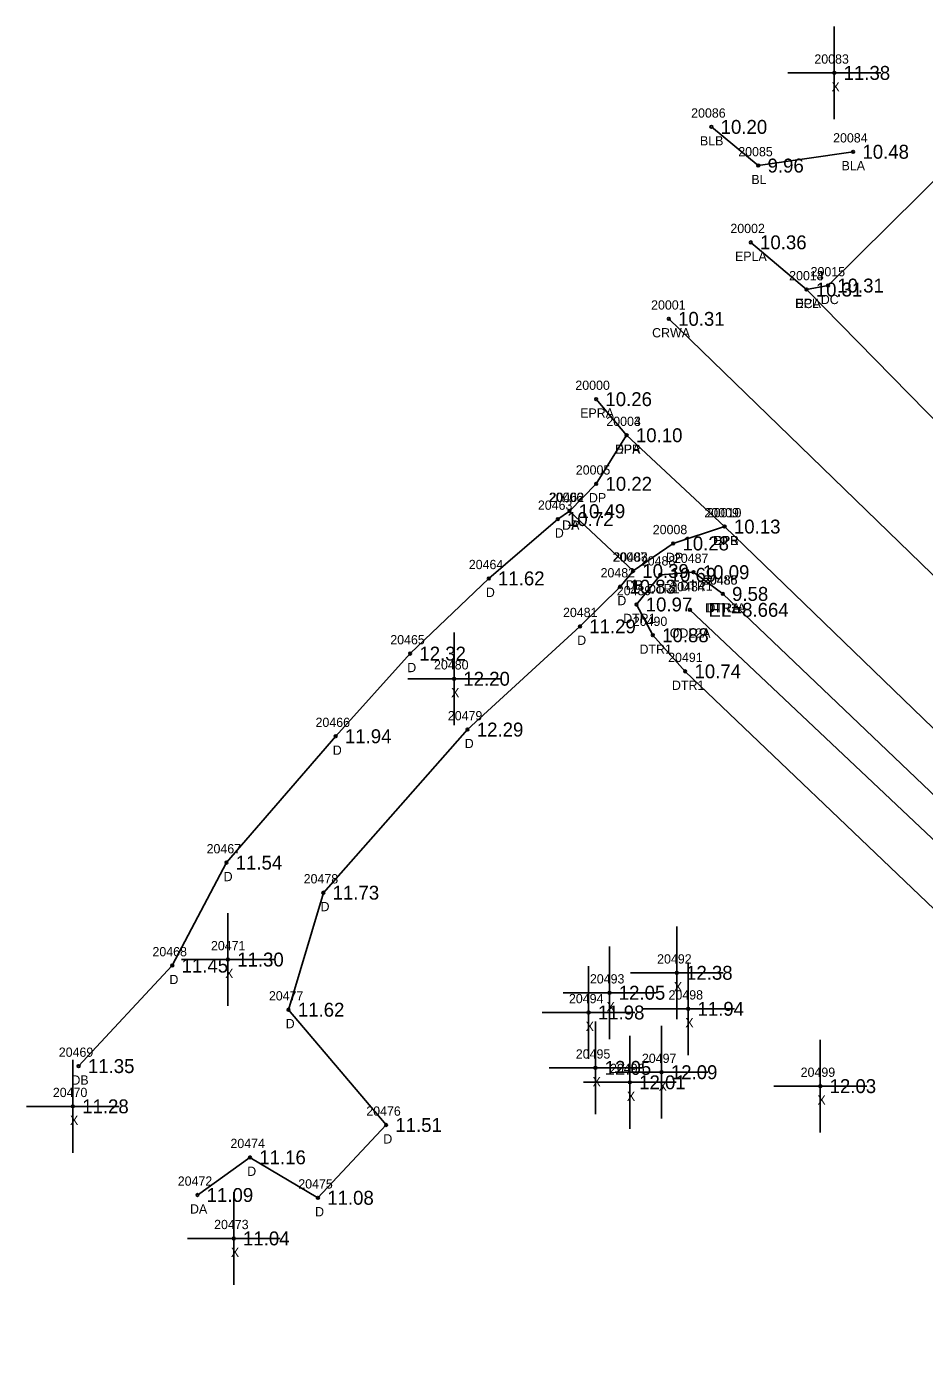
# Model space of a CAD drawing. Extents: x 2608745 to 2610333, y 641917 to 643463.
# Drawn here: x 2608745.5 to 2608842.3, y 643262.1 to 643405.2 of the extents above; entities that cross this region are included whole.
import ezdxf

# ---------------------------------------------------------------- set-up
doc = ezdxf.new("R2010")
doc.units = 0
for name, color, linetype in [('RD_DTM_BkLn1', 7, 'Continuous'), ('RD_DTM_BkLn_txCode', 7, 'Continuous'), ('RD_EX_Conc', 7, 'Continuous'), ('RD_EX_Conc_txCode', 7, 'Continuous'), ('RD_EX_Driveway', 7, 'Continuous'), ('RD_EX_Driveway_txCode', 7, 'Continuous'), ('RD_EX_H2O', 7, 'Continuous'), ('RD_EX_H2O_txCode', 7, 'Continuous'), ('RD_EX_Misc', 7, 'Continuous'), ('RD_EX_Misc_txCode', 7, 'Continuous'), ('RD_EX_Road', 7, 'Continuous'), ('RD_EX_Road_txCode', 7, 'Continuous'), ('RD_EX_TX_Conc_ELEV', 7, 'Continuous'), ('RD_EX_TX_Driveway_ELEV', 7, 'Continuous'), ('RD_EX_TX_H2O_ELEV', 7, 'Continuous'), ('RD_EX_TX_Misc_ELEV', 7, 'Continuous'), ('RD_EX_TX_Road_ELEV', 7, 'Continuous'), ('RD_HC_Survey_ELEV', 7, 'Continuous'), ('RD_HC_Survey_txCode', 7, 'Continuous'), ('RD_SMD_Locator', 7, 'Continuous')]:
    doc.layers.add(name, color=color, linetype=linetype)

msp = doc.modelspace()

# ---------------------------------------------------------------- linework, layer by layer
at = {"layer": 'RD_DTM_BkLn1'}
for points in [[(2608834.61, 643391.67), (2608824.38, 643390.18), (2608819.32, 643394.35)], [(2608814.73, 643373.65), (2608890.45, 643300.26), (2608962.19, 643231.31), (2609034.91, 643161.19), (2609108.48, 643089.9), (2609179.19, 643022.29), (2609255.71, 642948.78), (2609335.19, 642871.73), (2609410.7, 642798.48), (2609491.67, 642719.95), (2609518.07, 642695.15)]]:
    msp.add_lwpolyline(points, dxfattribs=at)
at = {"layer": 'RD_EX_Conc'}
msp.add_lwpolyline([(2608829.58, 643376.81), (2608831.9, 643377.24), (2608848.38, 643393.52)], dxfattribs=at)
at = {"layer": 'RD_EX_Driveway'}
for points in [[(2608810.18, 643361.1), (2608806.9, 643355.86), (2608804.01, 643352.91), (2608810.87, 643346.46), (2608815.2, 643349.43), (2608820.75, 643351.25)], [(2608804.01, 643352.91), (2608802.75, 643352.06), (2608795.31, 643345.66), (2608786.83, 643337.55), (2608778.8, 643328.64), (2608767.02, 643315.01), (2608761.18, 643303.91), (2608751.08, 643293.07)], [(2608763.89, 643279.17), (2608769.56, 643283.23), (2608776.89, 643278.87), (2608784.24, 643286.72), (2608773.72, 643299.15), (2608777.47, 643311.77), (2608793.02, 643329.36), (2608805.15, 643340.49), (2608809.48, 643344.77), (2608810.87, 643346.46)]]:
    msp.add_lwpolyline(points, dxfattribs=at)
at = {"layer": 'RD_EX_H2O'}
for points in [[(2608820.55, 643343.99), (2608817.4, 643346.33), (2608813.82, 643346.05), (2608811.24, 643342.85), (2608813.01, 643339.53), (2608816.5, 643335.64), (2608871.77, 643282.86), (2608887.42, 643272.57)], [(2608820.55, 643343.99), (2608878.38, 643288.9), (2608899.7, 643269.64), (2608901.3, 643266.14), (2608896.99, 643263), (2608887.42, 643272.57)], [(2608817.01, 643342.27), (2608875.55, 643287.01), (2608897.37, 643266.54)]]:
    msp.add_lwpolyline(points, dxfattribs=at)
at = {"layer": 'RD_EX_Misc'}
for p, q in [((2608832.58, 643395.17), (2608832.58, 643405.17)), ((2608827.58, 643400.17), (2608837.58, 643400.17)), ((2608791.57, 643329.84), (2608791.57, 643339.84)), ((2608786.57, 643334.84), (2608796.57, 643334.84)), ((2608767.18, 643299.56), (2608767.18, 643309.56)), ((2608815.59, 643298.13), (2608815.59, 643308.13)), ((2608808.33, 643295.98), (2608808.33, 643305.98)), ((2608762.18, 643304.56), (2608772.18, 643304.56)), ((2608816.82, 643294.25), (2608816.82, 643304.25)), ((2608806.08, 643293.85), (2608806.08, 643303.85)), ((2608810.59, 643303.13), (2608820.59, 643303.13)), ((2608803.33, 643300.98), (2608813.33, 643300.98)), ((2608801.08, 643298.85), (2608811.08, 643298.85)), ((2608811.82, 643299.25), (2608821.82, 643299.25)), ((2608806.81, 643287.88), (2608806.81, 643297.88)), ((2608813.95, 643287.41), (2608813.95, 643297.41)), ((2608810.53, 643286.32), (2608810.53, 643296.32)), ((2608831.07, 643285.91), (2608831.07, 643295.91)), ((2608750.46, 643283.73), (2608750.46, 643293.73)), ((2608801.81, 643292.88), (2608811.81, 643292.88)), ((2608808.95, 643292.41), (2608818.95, 643292.41)), ((2608805.53, 643291.32), (2608815.53, 643291.32)), ((2608826.07, 643290.91), (2608836.07, 643290.91)), ((2608745.46, 643288.73), (2608755.46, 643288.73)), ((2608767.81, 643269.49), (2608767.81, 643279.49)), ((2608762.81, 643274.49), (2608772.81, 643274.49))]:
    msp.add_line(p, q, dxfattribs=at)
at = {"layer": 'RD_EX_Road'}
for points in [[(2608823.57, 643381.9), (2608829.58, 643376.81), (2608846.19, 643359.9), (2608852.07, 643354.1), (2608873.12, 643334.61), (2608877.91, 643330.13), (2608897.26, 643311.51), (2608898.77, 643309.3), (2608970.3, 643240.18), (2609042.49, 643170.94), (2609058.51, 643155.46), (2609096.06, 643119.37)], [(2608806.89, 643364.99), (2608810.18, 643361.1), (2608820.75, 643351.25), (2608881.81, 643292.24), (2608917.83, 643257.49), (2608933.21, 643242.71), (2608954.07, 643222.83), (2609026.06, 643154.19), (2609039.6, 643139.96), (2609073.88, 643106.95), (2609100.48, 643081.89), (2609124.19, 643058.87), (2609171.61, 643013.71), (2609183.19, 643002.28), (2609197.91, 642988.37), (2609247.59, 642940.95), (2609328.02, 642863.6), (2609402.61, 642790.3), (2609474.23, 642720.69), (2609483.84, 642711.58), (2609495.78, 642699.92), (2609509.81, 642686.45)]]:
    msp.add_lwpolyline(points, dxfattribs=at)
at = {"layer": 'RD_SMD_Locator'}
for centre in [(2608832.58, 643400.17), (2608819.32, 643394.35), (2608834.61, 643391.67), (2608824.38, 643390.18), (2608823.57, 643381.9), (2608831.9, 643377.24), (2608829.58, 643376.81), (2608829.58, 643376.81), (2608814.73, 643373.65), (2608806.89, 643364.99), (2608810.18, 643361.1), (2608810.18, 643361.1), (2608806.9, 643355.86), (2608804.01, 643352.91), (2608804.01, 643352.91), (2608802.75, 643352.06), (2608820.75, 643351.25), (2608820.75, 643351.25), (2608815.2, 643349.43), (2608795.31, 643345.66), (2608810.87, 643346.46), (2608810.87, 643346.46), (2608813.82, 643346.05), (2608817.4, 643346.33), (2608809.48, 643344.77), (2608811.24, 643342.85), (2608820.55, 643343.99), (2608820.55, 643343.99), (2608817.01, 643342.27), (2608805.15, 643340.49), (2608813.01, 643339.53), (2608786.83, 643337.55), (2608816.5, 643335.64), (2608791.57, 643334.84), (2608778.8, 643328.64), (2608793.02, 643329.36), (2608767.02, 643315.01), (2608777.47, 643311.77), (2608767.18, 643304.56), (2608761.18, 643303.91), (2608815.59, 643303.13), (2608808.33, 643300.98), (2608773.72, 643299.15), (2608806.08, 643298.85), (2608816.82, 643299.25), (2608751.08, 643293.07), (2608806.81, 643292.88), (2608810.53, 643291.32), (2608813.95, 643292.41), (2608831.07, 643290.91), (2608750.46, 643288.73), (2608784.24, 643286.72), (2608769.56, 643283.23), (2608763.89, 643279.17), (2608776.89, 643278.87), (2608767.81, 643274.49)]:
    msp.add_circle(centre, 0.15, dxfattribs=at)

# ---------------------------------------------------------------- texts
at = {"layer": 'RD_DTM_BkLn_txCode'}
for s, p in [('20086', (2608817.14, 643395.35)), ('BLB', (2608818.09, 643392.35)), ('20084', (2608832.45, 643392.67)), ('20085', (2608822.22, 643391.18)), ('BLA', (2608833.36, 643389.67)), ('BL', (2608823.63, 643388.18))]:
    msp.add_text(s, height=1, dxfattribs=at).set_placement(p)
at = {"layer": 'RD_EX_Conc_txCode'}
for s, p in [('20014', (2608827.71, 643377.81)), ('20015', (2608830.02, 643378.24)), ('DCA', (2608828.32, 643374.81)), ('DC', (2608831.12, 643375.24))]:
    msp.add_text(s, height=1, dxfattribs=at).set_placement(p)
at = {"layer": 'RD_EX_Driveway_txCode'}
for s, p in [('20004', (2608807.99, 643362.1)), ('DPA', (2608808.92, 643359.1)), ('20005', (2608804.7, 643356.86)), ('20006', (2608801.79, 643353.91)), ('20462', (2608801.87, 643353.91)), ('DP', (2608806.12, 643353.86)), ('20463', (2608800.61, 643353.06)), ('20009', (2608818.56, 643352.25)), ('DA', (2608803.22, 643350.91)), ('DP', (2608803.24, 643350.91)), ('D', (2608802.44, 643350.06)), ('20008', (2608813, 643350.43)), ('DPB', (2608819.5, 643349.25)), ('20464', (2608793.16, 643346.66)), ('20007', (2608808.67, 643347.46)), ('20483', (2608808.75, 643347.46)), ('DP', (2608814.42, 643347.43)), ('20482', (2608807.37, 643345.77)), ('D', (2608795, 643343.66)), ('DP', (2608810.09, 643344.46)), ('DB', (2608810.09, 643344.46)), ('D', (2608809.18, 643342.77)), ('20481', (2608803.32, 643341.49)), ('20465', (2608784.69, 643338.55)), ('D', (2608804.85, 643338.49)), ('D', (2608786.52, 643335.55)), ('20466', (2608776.63, 643329.64)), ('20479', (2608790.9, 643330.36)), ('D', (2608778.49, 643326.64)), ('D', (2608792.72, 643327.36)), ('20467', (2608764.88, 643316.01)), ('D', (2608766.72, 643313.01)), ('20478', (2608775.35, 643312.77)), ('D', (2608777.17, 643309.77)), ('20468', (2608759.04, 643304.91)), ('D', (2608760.87, 643301.91)), ('20477', (2608771.6, 643300.15)), ('D', (2608773.41, 643297.15)), ('20469', (2608748.94, 643294.07)), ('DB', (2608750.3, 643291.07)), ('20476', (2608782.1, 643287.72)), ('D', (2608783.94, 643284.72)), ('20474', (2608767.45, 643284.23)), ('D', (2608769.26, 643281.23)), ('20472', (2608761.77, 643280.17)), ('20475', (2608774.77, 643279.87)), ('DA', (2608763.09, 643277.17)), ('D', (2608776.58, 643276.87))]:
    msp.add_text(s, height=1, dxfattribs=at).set_placement(p)
at = {"layer": 'RD_EX_H2O_txCode'}
for s, p in [('20488', (2608811.71, 643347.05)), ('20487', (2608815.28, 643347.33)), ('20486', (2608818.4, 643344.99)), ('20485', (2608818.43, 643344.99)), ('20489', (2608809.12, 643343.85)), ('DTR1', (2608812.39, 643344.05)), ('20484', (2608814.89, 643344.27)), ('DTR1', (2608815.97, 643344.33)), ('DTR1A', (2608818.63, 643341.99)), ('DTRA', (2608818.79, 643341.99)), ('DTR1', (2608809.81, 643340.85)), ('20490', (2608810.85, 643340.53)), ('ODL2A', (2608814.83, 643339.27)), ('DTR1', (2608811.57, 643337.53)), ('20491', (2608814.66, 643336.64)), ('DTR1', (2608815.07, 643333.64))]:
    msp.add_text(s, height=1, dxfattribs=at).set_placement(p)
at = {"layer": 'RD_EX_Misc_txCode'}
for s, p in [('20083', (2608830.43, 643401.17)), ('X', (2608832.27, 643398.17)), ('20480', (2608789.41, 643335.84)), ('X', (2608791.25, 643332.84)), ('20471', (2608765.35, 643305.56)), ('20492', (2608813.47, 643304.13)), ('X', (2608766.87, 643302.56)), ('20493', (2608806.22, 643301.98)), ('X', (2608815.27, 643301.13)), ('20494', (2608803.96, 643299.85)), ('X', (2608808.02, 643298.98)), ('20498', (2608814.7, 643300.25)), ('X', (2608805.76, 643296.85)), ('X', (2608816.51, 643297.25)), ('20495', (2608804.7, 643293.88)), ('20497', (2608811.83, 643293.41)), ('20496', (2608808.39, 643292.32)), ('20499', (2608828.95, 643291.91)), ('X', (2608806.5, 643290.88)), ('X', (2608813.63, 643290.41)), ('20470', (2608748.3, 643289.73)), ('X', (2608810.21, 643289.32)), ('X', (2608830.76, 643288.91)), ('X', (2608750.15, 643286.73)), ('20473', (2608765.69, 643275.49)), ('X', (2608767.5, 643272.49))]:
    msp.add_text(s, height=1, dxfattribs=at).set_placement(p)
at = {"layer": 'RD_EX_Road_txCode'}
for s, p in [('20002', (2608821.37, 643382.9)), ('EPLA', (2608821.87, 643379.9)), ('20013', (2608827.71, 643377.81)), ('EPL', (2608828.38, 643374.81)), ('20000', (2608804.65, 643365.99)), ('EPRA', (2608805.17, 643362.99)), ('20003', (2608807.99, 643362.1)), ('EPR', (2608808.96, 643359.1)), ('20010', (2608818.84, 643352.25)), ('EPR', (2608819.53, 643349.25))]:
    msp.add_text(s, height=1, dxfattribs=at).set_placement(p)
at = {"layer": 'RD_EX_TX_Conc_ELEV'}
for p in [(2608830.58, 643376.06), (2608832.9, 643376.49)]:
    msp.add_text('10.31', height=1.5, dxfattribs=at).set_placement(p)
at = {"layer": 'RD_EX_TX_Driveway_ELEV'}
for s, p in [('10.10', (2608811.18, 643360.35)), ('10.22', (2608807.9, 643355.11)), ('10.49', (2608805.01, 643352.16)), ('10.49', (2608805.01, 643352.16)), ('10.72', (2608803.75, 643351.31)), ('10.13', (2608821.75, 643350.5)), ('10.28', (2608816.2, 643348.68)), ('10.39', (2608811.87, 643345.71)), ('10.39', (2608811.87, 643345.71)), ('11.62', (2608796.31, 643344.91)), ('10.83', (2608810.48, 643344.02)), ('11.29', (2608806.15, 643339.74)), ('12.32', (2608787.83, 643336.8)), ('12.29', (2608794.02, 643328.61)), ('11.94', (2608779.8, 643327.89)), ('11.54', (2608768.02, 643314.26)), ('11.73', (2608778.47, 643311.02)), ('11.45', (2608762.18, 643303.16)), ('11.62', (2608774.72, 643298.4)), ('11.35', (2608752.08, 643292.32)), ('11.51', (2608785.24, 643285.97)), ('11.16', (2608770.56, 643282.48)), ('11.09', (2608764.89, 643278.42)), ('11.08', (2608777.89, 643278.12))]:
    msp.add_text(s, height=1.5, dxfattribs=at).set_placement(p)
at = {"layer": 'RD_EX_TX_H2O_ELEV'}
for s, p in [('10.69', (2608814.82, 643345.3)), ('10.09', (2608818.4, 643345.58)), ('9.58', (2608821.55, 643343.24)), ('9.58', (2608821.55, 643343.24)), ('10.97', (2608812.24, 643342.1)), ('EL=8.664', (2608819.01, 643341.52)), ('10.88', (2608814.01, 643338.78)), ('10.74', (2608817.5, 643334.89))]:
    msp.add_text(s, height=1.5, dxfattribs=at).set_placement(p)
at = {"layer": 'RD_EX_TX_Misc_ELEV'}
for s, p in [('11.38', (2608833.58, 643399.42)), ('10.20', (2608820.32, 643393.6)), ('10.48', (2608835.61, 643390.92)), ('9.96', (2608825.38, 643389.43)), ('12.20', (2608792.57, 643334.09)), ('11.30', (2608768.18, 643303.81)), ('12.38', (2608816.59, 643302.38)), ('12.05', (2608809.33, 643300.23)), ('11.94', (2608817.82, 643298.5)), ('11.98', (2608807.08, 643298.1)), ('12.05', (2608807.81, 643292.13)), ('12.09', (2608814.95, 643291.66)), ('12.01', (2608811.53, 643290.57)), ('12.03', (2608832.07, 643290.16)), ('11.28', (2608751.46, 643287.98)), ('11.04', (2608768.81, 643273.74))]:
    msp.add_text(s, height=1.5, dxfattribs=at).set_placement(p)
at = {"layer": 'RD_EX_TX_Road_ELEV'}
for s, p in [('10.36', (2608824.57, 643381.15)), ('10.31', (2608830.58, 643376.06)), ('10.26', (2608807.89, 643364.24)), ('10.10', (2608811.18, 643360.35)), ('10.13', (2608821.75, 643350.5))]:
    msp.add_text(s, height=1.5, dxfattribs=at).set_placement(p)
at = {"layer": 'RD_HC_Survey_ELEV'}
msp.add_text('10.31', height=1.5, dxfattribs=at).set_placement((2608815.73, 643372.9))
at = {"layer": 'RD_HC_Survey_txCode'}
for s, p in [('20001', (2608812.82, 643374.65)), ('CRWA', (2608812.93, 643371.65))]:
    msp.add_text(s, height=1, dxfattribs=at).set_placement(p)

doc.saveas('drawing.dxf')
